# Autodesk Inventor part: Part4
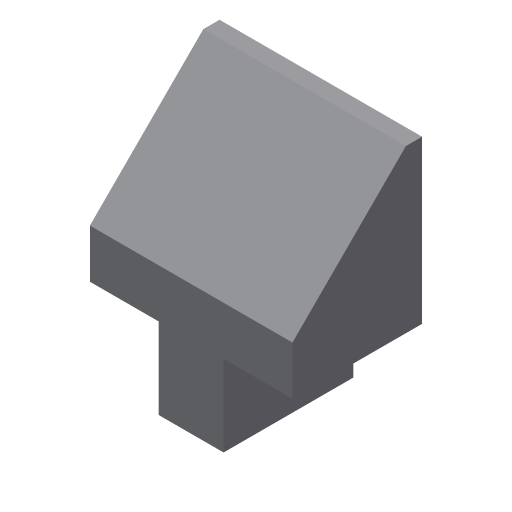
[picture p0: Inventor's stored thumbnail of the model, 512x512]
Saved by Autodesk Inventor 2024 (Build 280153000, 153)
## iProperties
Shininess: 77.0
Length Units: 11269
Angle Units: 11279
Time Units: 11290
Mass Units: 11283
Length Display Precision: 3
Angle Display Precision: 2
Created: 2002-01
Part Number: Part4
Document SubType Name: Modeling
Designer: ***
Density: 1 g/cm^3
Material: Generic
Appearance: Default
Density: 0.0
Volumn: 0.0
Area: 0.0
PropertySet Name: Model Information
Control State: 0
Master: False
Checked Out: False
Author: ***
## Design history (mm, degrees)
sketch "Sketch2"
  geometry: L1 (2.32, -6.969)-(2.32, 13.031); L2 (2.32, 13.031)-(0.32, 13.031); L3 (0.32, 13.031)-(-13.68, -0.969); L4 (-13.68, -0.969)-(-13.68, -6.969); L5 (-13.68, -6.969)-(2.32, -6.969)
  constraints: 10 end point, 2 parallel, 1 perpendicular, 1 vertical
  dimensions: "d0" = 2 distance of L1.end L2.end; "d1" = 135 deg angle of L4 L3; "d2" = 20 distance of L1.start L1.end; "d3" = 16 distance of L4.end L1.start
extrude "Extrusion1" new body sketch "Sketch2" stored distance "d4" = 25; taper "d5" = 0 deg
sketch "Sketch3"
  geometry: L1 (-13.68, -6.969)-(2.32, -6.969); L2 (2.32, -6.969)-(2.32, -16.969); L3 (2.32, -16.969)-(-13.68, -16.969); L4 (-13.68, -16.969)-(-13.68, -6.969); L5 (-13.68, -6.969)-(2.32, -6.969) reference; L6 (-13.68, -0.969)-(-13.68, -6.969) reference; L7 (2.32, -6.969)-(2.32, 13.031) reference
  constraints: 8 end point, 3 collinear, 2 parallel, 1 horizontal, 1 perpendicular
  dimensions: "d6" = 10 distance of L3.end L1.start
extrude "Extrusion2" join sketch "Sketch3" stored distance "d7" = 8; taper "d8" = 0 deg
body "Solid1"
